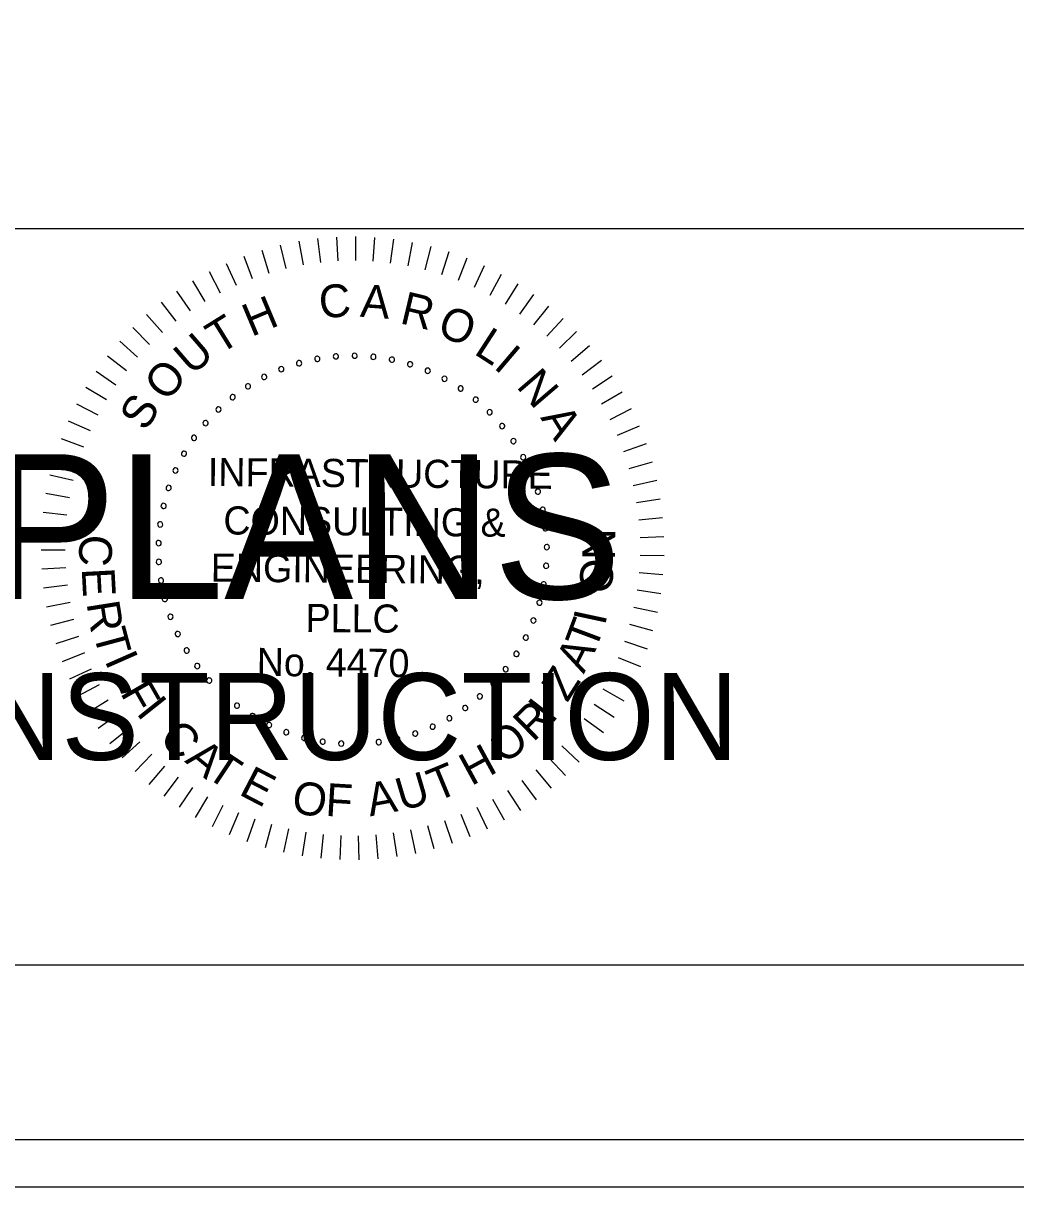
# Model space of a CAD drawing. Extents: x 967 to 1326, y 964 to 2584.
# Drawn here: x 1189.3 to 1212.88, y 963.72 to 991.36 of the extents above; entities that cross this region are included whole.
import ezdxf

# ---------------------------------------------------------------- set-up
doc = ezdxf.new("R2010")
doc.units = 0
for name, color, linetype in [('RD_SHT_Misc1', 7, 'Continuous'), ('RD_SHT_Misc2', 7, 'Continuous'), ('RD_XS_ExPaveRet', 7, 'Continuous'), ('RD_XS_TX_Elev_EX', 7, 'Continuous')]:
    doc.layers.add(name, color=color, linetype=linetype)

msp = doc.modelspace()

# ---------------------------------------------------------------- linework, layer by layer
at = {"layer": 'RD_SHT_Misc1'}
for p, q in [((1196.292, 986.245), (1196.357, 985.68)), ((1196.742, 986.282), (1196.772, 985.714)), ((1197.194, 986.292), (1197.189, 985.723)), ((1197.645, 986.274), (1197.606, 985.706)), ((1198.094, 986.228), (1198.02, 985.664)), ((1194.968, 985.971), (1195.134, 985.427)), ((1195.403, 986.09), (1195.536, 985.536)), ((1195.846, 986.181), (1195.945, 985.62)), ((1198.54, 986.156), (1198.432, 985.596)), ((1198.98, 986.056), (1198.838, 985.504)), ((1199.414, 985.929), (1199.238, 985.387)), ((1194.122, 985.656), (1194.353, 985.136)), ((1194.54, 985.827), (1194.739, 985.293)), ((1199.839, 985.777), (1199.63, 985.246)), ((1193.715, 985.461), (1193.978, 984.956)), ((1200.253, 985.598), (1200.013, 985.082)), ((1200.656, 985.395), (1200.385, 984.894)), ((1193.321, 985.241), (1193.614, 984.752)), ((1201.047, 985.167), (1200.745, 984.684)), ((1192.94, 984.997), (1193.263, 984.528)), ((1201.422, 984.917), (1201.092, 984.453)), ((1192.576, 984.731), (1192.926, 984.282)), ((1201.781, 984.643), (1201.424, 984.2)), ((1192.228, 984.443), (1192.605, 984.016)), ((1202.124, 984.349), (1201.739, 983.928)), ((1191.899, 984.134), (1192.301, 983.731)), ((1202.447, 984.034), (1202.038, 983.638)), ((1191.589, 983.805), (1192.015, 983.428)), ((1202.751, 983.7), (1202.318, 983.329)), ((1191.299, 983.459), (1191.748, 983.108)), ((1203.034, 983.348), (1202.579, 983.004)), ((1191.032, 983.095), (1191.501, 982.772)), ((1203.294, 982.979), (1202.82, 982.664)), ((1190.787, 982.716), (1191.274, 982.422)), ((1203.532, 982.595), (1203.04, 982.31)), ((1190.565, 982.323), (1191.07, 982.059)), ((1203.746, 982.198), (1203.237, 981.943)), ((1190.368, 981.916), (1190.888, 981.684)), ((1203.936, 981.788), (1203.412, 981.564)), ((1190.196, 981.499), (1190.729, 981.299)), ((1204.1, 981.367), (1203.563, 981.176)), ((1190.05, 981.072), (1190.594, 980.905)), ((1204.238, 980.937), (1203.691, 980.779)), ((1189.93, 980.636), (1190.484, 980.503)), ((1204.349, 980.5), (1203.794, 980.375)), ((1189.837, 980.195), (1190.398, 980.095)), ((1204.434, 980.056), (1203.872, 979.966)), ((1189.771, 979.748), (1190.337, 979.683)), ((1204.491, 979.608), (1203.925, 979.552)), ((1189.732, 979.298), (1190.301, 979.267)), ((1204.522, 979.158), (1203.953, 979.137)), ((1189.721, 978.847), (1190.29, 978.851)), ((1204.524, 978.706), (1203.955, 978.72)), ((1189.737, 978.396), (1190.306, 978.434)), ((1204.499, 978.256), (1203.932, 978.304)), ((1189.781, 977.946), (1190.346, 978.019)), ((1204.447, 977.807), (1203.884, 977.89)), ((1189.852, 977.5), (1190.412, 977.608)), ((1204.367, 977.363), (1203.81, 977.479)), ((1189.951, 977.06), (1190.502, 977.201)), ((1204.261, 976.924), (1203.712, 977.074)), ((1190.076, 976.626), (1190.617, 976.8)), ((1204.128, 976.492), (1203.589, 976.676)), ((1190.227, 976.2), (1190.757, 976.408)), ((1203.969, 976.07), (1203.442, 976.286)), ((1190.403, 975.785), (1190.92, 976.024)), ((1203.784, 975.658), (1203.271, 975.906)), ((1190.605, 975.381), (1191.106, 975.651)), ((1203.574, 975.258), (1203.078, 975.537)), ((1190.831, 974.99), (1191.315, 975.291)), ((1203.341, 974.871), (1202.862, 975.18)), ((1191.081, 974.614), (1191.545, 974.943)), ((1191.353, 974.253), (1191.796, 974.61)), ((1203.085, 974.5), (1202.626, 974.837)), ((1202.806, 974.145), (1202.368, 974.509)), ((1191.646, 973.91), (1192.067, 974.293)), ((1202.506, 973.807), (1202.092, 974.197)), ((1191.96, 973.585), (1192.356, 973.994)), ((1202.186, 973.488), (1201.796, 973.903)), ((1192.293, 973.28), (1192.664, 973.712)), ((1201.847, 973.19), (1201.484, 973.628)), ((1192.644, 972.996), (1192.988, 973.45)), ((1193.011, 972.734), (1193.327, 973.208)), ((1201.491, 972.912), (1201.155, 973.372)), ((1193.394, 972.495), (1193.68, 972.987)), ((1200.731, 972.425), (1200.453, 972.922)), ((1201.119, 972.657), (1200.811, 973.136)), ((1193.791, 972.279), (1194.047, 972.788)), ((1200.331, 972.217), (1200.083, 972.73)), ((1194.2, 972.088), (1194.424, 972.612)), ((1194.62, 971.923), (1194.812, 972.459)), ((1199.495, 971.877), (1199.312, 972.416)), ((1199.918, 972.034), (1199.702, 972.561)), ((1195.05, 971.783), (1195.208, 972.33)), ((1195.487, 971.67), (1195.612, 972.225)), ((1195.93, 971.584), (1196.021, 972.146)), ((1196.377, 971.524), (1196.434, 972.091)), ((1198.179, 971.562), (1198.097, 972.126)), ((1198.624, 971.64), (1198.508, 972.198)), ((1199.063, 971.745), (1198.913, 972.295)), ((1196.828, 971.493), (1196.85, 972.062)), ((1197.279, 971.488), (1197.267, 972.058)), ((1197.73, 971.512), (1197.683, 972.079))]:
    msp.add_line(p, q, dxfattribs=at)
for centre, start, end in [((1196.285, 983.388), 10.6038, 190.6038), ((1196.727, 983.447), 5.0653, 185.0653), ((1196.727, 983.447), 185.0653, 5.0653), ((1197.172, 983.464), 359.5268, 179.5268), ((1197.172, 983.464), 179.5268, 359.5268), ((1197.617, 983.438), 173.9884, 353.9884), ((1197.617, 983.438), 353.9884, 173.9884), ((1198.057, 983.369), 348.4499, 168.4499), ((1195.429, 983.142), 21.6807, 201.6807), ((1195.429, 983.142), 201.6807, 21.6807), ((1195.851, 983.285), 16.1422, 196.1422), ((1195.851, 983.285), 196.1422, 16.1422), ((1196.285, 983.388), 190.6038, 10.6038), ((1198.057, 983.369), 168.4499, 348.4499), ((1198.489, 983.258), 162.9114, 342.9114), ((1198.489, 983.258), 342.9114, 162.9114), ((1198.908, 983.106), 337.373, 157.373), ((1195.023, 982.958), 27.2191, 207.2191), ((1195.023, 982.958), 207.2191, 27.2191), ((1198.908, 983.106), 157.373, 337.373), ((1199.31, 982.914), 151.8345, 331.8345), ((1199.31, 982.914), 331.8345, 151.8345), ((1194.637, 982.736), 32.7576, 212.7576), ((1194.637, 982.736), 212.7576, 32.7576), ((1199.692, 982.684), 146.2961, 326.2961), ((1199.692, 982.684), 326.2961, 146.2961), ((1194.274, 982.478), 38.2961, 218.2961), ((1194.274, 982.478), 218.2961, 38.2961), ((1200.05, 982.419), 140.7576, 320.7576), ((1200.05, 982.419), 320.7576, 140.7576), ((1193.937, 982.186), 43.8345, 223.8345), ((1193.937, 982.186), 223.8345, 43.8345), ((1200.38, 982.12), 135.2191, 315.2191), ((1200.38, 982.12), 315.2191, 135.2191), ((1193.63, 981.862), 49.373, 229.373), ((1193.63, 981.862), 229.373, 49.373), ((1200.68, 981.79), 129.6807, 309.6807), ((1200.68, 981.79), 309.6807, 129.6807), ((1193.356, 981.511), 54.9114, 234.9114), ((1193.356, 981.511), 234.9114, 54.9114), ((1200.947, 981.433), 304.1422, 124.1422), ((1200.947, 981.433), 124.1422, 304.1422), ((1193.117, 981.135), 60.4499, 240.4499), ((1193.117, 981.135), 240.4499, 60.4499), ((1201.179, 981.052), 118.6038, 298.6038), ((1201.179, 981.052), 298.6038, 118.6038), ((1192.915, 980.737), 65.9884, 245.9884), ((1192.915, 980.737), 245.9884, 65.9884), ((1201.372, 980.651), 113.0653, 293.0653), ((1201.372, 980.651), 293.0653, 113.0653), ((1192.753, 980.322), 71.5268, 251.5268), ((1192.753, 980.322), 251.5268, 71.5268), ((1201.526, 980.233), 107.5268, 287.5268), ((1201.526, 980.233), 287.5268, 107.5268), ((1192.632, 979.894), 77.0653, 257.0653), ((1192.632, 979.894), 257.0653, 77.0653), ((1201.638, 979.801), 101.9884, 281.9884), ((1201.638, 979.801), 281.9884, 101.9884), ((1192.552, 979.455), 82.6038, 262.6038), ((1192.552, 979.455), 262.6038, 82.6038), ((1201.709, 979.361), 96.4499, 276.4499), ((1201.709, 979.361), 276.4499, 96.4499), ((1192.515, 979.011), 88.1422, 268.1422), ((1192.515, 979.011), 268.1422, 88.1422), ((1201.737, 978.917), 90.9114, 270.9114), ((1201.737, 978.917), 270.9114, 90.9114), ((1192.522, 978.565), 93.6807, 273.6807), ((1192.522, 978.565), 273.6807, 93.6807), ((1201.721, 978.471), 85.373, 265.373), ((1201.721, 978.471), 265.373, 85.373), ((1192.571, 978.122), 99.2191, 279.2191), ((1192.571, 978.122), 279.2191, 99.2191), ((1201.663, 978.029), 79.8345, 259.8345), ((1201.663, 978.029), 259.8345, 79.8345), ((1192.662, 977.686), 104.7576, 284.7576), ((1192.662, 977.686), 284.7576, 104.7576), ((1201.563, 977.595), 74.2961, 254.2961), ((1201.563, 977.595), 254.2961, 74.2961), ((1192.796, 977.261), 110.2961, 290.2961), ((1192.796, 977.261), 290.2961, 110.2961), ((1201.42, 977.173), 68.7576, 248.7576), ((1201.42, 977.173), 248.7576, 68.7576), ((1192.97, 976.851), 115.8345, 295.8345), ((1192.97, 976.851), 295.8345, 115.8345), ((1201.238, 976.766), 63.2191, 243.2191), ((1201.238, 976.766), 243.2191, 63.2191), ((1193.182, 976.459), 301.373, 121.373), ((1193.182, 976.459), 121.373, 301.373), ((1201.018, 976.379), 57.6807, 237.6807), ((1201.018, 976.379), 237.6807, 57.6807), ((1193.432, 976.09), 126.9114, 306.9114), ((1193.432, 976.09), 306.9114, 126.9114), ((1200.761, 976.014), 52.1422, 232.1422), ((1200.761, 976.014), 232.1422, 52.1422), ((1193.715, 975.746), 132.4499, 312.4499), ((1193.715, 975.746), 312.4499, 132.4499), ((1200.47, 975.677), 46.6038, 226.6038), ((1200.47, 975.677), 226.6038, 46.6038), ((1194.031, 975.431), 137.9884, 317.9884), ((1194.031, 975.431), 317.9884, 137.9884), ((1200.148, 975.369), 41.0653, 221.0653), ((1200.148, 975.369), 221.0653, 41.0653), ((1194.376, 975.149), 143.5268, 323.5268), ((1194.376, 975.149), 323.5268, 143.5268), ((1199.798, 975.093), 35.5268, 215.5268), ((1194.746, 974.901), 149.0653, 329.0653), ((1194.746, 974.901), 329.0653, 149.0653), ((1199.422, 974.853), 29.9884, 209.9884), ((1199.422, 974.853), 209.9884, 29.9884), ((1199.798, 975.093), 215.5268, 35.5268), ((1195.139, 974.69), 154.6038, 334.6038), ((1195.139, 974.69), 334.6038, 154.6038), ((1195.55, 974.517), 340.1422, 160.1422), ((1199.026, 974.65), 24.4499, 204.4499), ((1199.026, 974.65), 204.4499, 24.4499), ((1195.55, 974.517), 160.1422, 340.1422), ((1195.975, 974.386), 165.6807, 345.6807), ((1195.975, 974.386), 345.6807, 165.6807), ((1196.412, 974.295), 171.2191, 351.2191), ((1196.412, 974.295), 351.2191, 171.2191), ((1196.855, 974.248), 356.7576, 176.7576), ((1197.301, 974.243), 2.2961, 182.2961), ((1197.745, 974.282), 7.8345, 187.8345), ((1198.183, 974.363), 13.373, 193.373), ((1198.183, 974.363), 193.373, 13.373), ((1198.611, 974.486), 18.9114, 198.9114), ((1198.611, 974.486), 198.9114, 18.9114), ((1196.855, 974.248), 176.7576, 356.7576), ((1197.301, 974.243), 182.2961, 2.2961), ((1197.745, 974.282), 187.8345, 7.8345)]:
    msp.add_arc(centre, 0.0627, start, end, dxfattribs=at)
at = {"layer": 'RD_XS_ExPaveRet'}
for points in [[(967.409, 963.72), (1326.285, 963.72), (1326.285, 1183.72), (967.409, 1183.72)], [(988.525, 964.84), (1326.285, 964.84), (1326.285, 1182.6), (988.525, 1182.6)]]:
    msp.add_lwpolyline(points, close=True, dxfattribs=at)
at = {"layer": 'RD_XS_TX_Elev_EX'}
for p, q in [((996.114, 986.486), (1323.886, 986.486)), ((1323.886, 968.983), (996.114, 968.983))]:
    msp.add_line(p, q, dxfattribs=at)

# ---------------------------------------------------------------- texts
at = {"layer": 'RD_SHT_Misc1'}
for s, height, rotation, p in [('C', 0.78, 4.7281, (1196.355, 984.346)), ('A', 0.78, 355.6981, (1197.29, 984.39)), ('H', 0.78, 22.7882, (1194.72, 983.904)), ('R', 0.78, 346.6681, (1198.222, 984.238)), ('O', 0.78, 337.638, (1199.096, 983.972)), ('T', 0.78, 31.8182, (1193.961, 983.478)), ('U', 0.78, 40.8482, (1193.306, 982.976)), ('L', 0.78, 327.108, (1199.981, 983.52)), ('I', 0.78, 319.578, (1200.451, 983.182)), ('O', 0.78, 49.8782, (1192.707, 982.341)), ('N', 0.78, 310.548, (1200.994, 982.728)), ('S', 0.78, 58.9083, (1192.211, 981.642)), ('A', 0.78, 301.5179, (1201.576, 981.991)), ('INFRASTRUCTURE', 0.66873, 359.5268, (1193.682, 980.367)), ('CONSULTING &', 0.66873, 359.5268, (1194.051, 979.217)), ('N', 0.78, 89.2085, (1203.359, 978.604)), ('C', 0.78, 267.025, (1190.646, 979.227)), ('ENGINEERING,', 0.66873, 359.5268, (1193.751, 978.095)), ('O', 0.78, 83.2085, (1203.26, 977.786)), ('E', 0.78, 273.025, (1190.685, 978.408)), ('R', 0.78, 279.025, (1190.799, 977.583)), ('PLLC', 0.6687, 359.5268, (1196.002, 976.9)), ('I', 0.78, 77.9093, (1203.121, 977.032)), ('T', 0.78, 69.3954, (1202.891, 976.428)), ('T', 0.78, 285.025, (1190.955, 976.878)), ('No. 4470', 0.6687, 359.5268, (1194.843, 975.855)), ('A', 0.78, 63.3954, (1202.616, 975.888)), ('I', 0.78, 293.7713, (1191.221, 976.225)), ('Z', 0.78, 57.3954, (1202.224, 975.206)), ('F', 0.78, 299.7713, (1191.589, 975.455)), ('I', 0.78, 308.5268, (1191.965, 974.973)), ('R', 0.78, 44.5268, (1201.415, 974.267)), ('I', 0.78, 52.3339, (1201.856, 974.69)), ('C', 0.78, 314.5268, (1192.496, 974.346)), ('O', 0.78, 38.5268, (1200.73, 973.731)), ('A', 0.78, 320.5268, (1193.115, 973.822)), ('T', 0.78, 326.5268, (1193.602, 973.478)), ('H', 0.78, 28.5268, (1199.942, 973.23)), ('T', 0.78, 22.5268, (1199.108, 972.856)), ('E', 0.78, 332.5268, (1194.394, 973.051)), ('U', 0.78, 16.5268, (1198.288, 972.638)), ('O', 0.78, 350.5268, (1195.647, 972.614)), ('F', 0.78, 356.5268, (1196.465, 972.532)), ('A', 0.78, 10.5268, (1197.537, 972.517))]:
    msp.add_text(s, height=height, rotation=rotation, dxfattribs=at).set_placement(p)
at = {"layer": 'RD_SHT_Misc2'}
for s, height, p in [('FINAL PLANS', 3.4375, (1174.145, 977.685)), ('NOT FOR CONSTRUCTION', 2.0625, (1170.901, 973.86))]:
    msp.add_text(s, height=height, dxfattribs=at).set_placement(p)

doc.saveas('drawing.dxf')
